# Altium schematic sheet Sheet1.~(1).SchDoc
size A; SheetNumber: 1; SheetTotal: 1
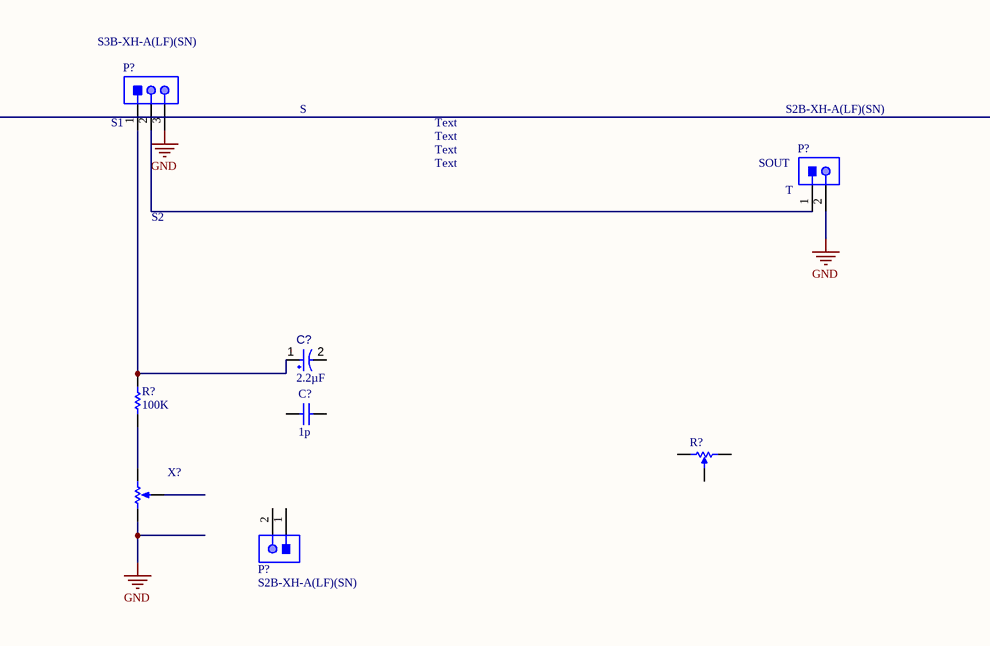
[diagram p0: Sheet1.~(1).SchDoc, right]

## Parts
(Parts that share a designator on the sheet are numbered #1, #2 ... from top to bottom, then left to right.)
C?#1  value 2.2µF  [CAPPR55-200-1100X500X1200]  (hidden comment: ECA1HM2R2)
C?#2  value 1p  (hidden comment: Capacitor)
P?#1  S3B-XH-A(LF)(SN)  [JST-S3B-XH-A(LF)(SN)_V]
P?#2  S2B-XH-A(LF)(SN)  [JST-S2B-XH-A(LF)(SN)_V]
P?#3  S2B-XH-A(LF)(SN)  [JST-S2B-XH-A(LF)(SN)_V]
R?#1  value 100K  (hidden comment: Resistor)
R?#2  3296W-1-102LF  [BOUR-3296W-1-3]  (value not drawn)
X?  Potentiometer  (value not drawn)

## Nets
GND: P?#1.3 P?#2.2 X?.1(TOP)
NetC?#1_1: C?#1.1 P?#1.1 R?#1.2
NetP?#1_2: P?#1.2 P?#2.1
NetR?#1_1: R?#1.1 X?.2(BOT)

Not connected (* = marked no-connect by the designer): C?#1 2; C?#2 1 2; P?#3 1 2; R?#2 1(A) 2(B) 3(TAP); X? 3(TAP)

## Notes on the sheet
- (near P?#1) S1
- S
- Text
- (near P?#2) SOUT
- (near P?#2) T
- S2

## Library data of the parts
C?#1 = CMP-001-00029-7: Aluminum Electrolytic Capacitor, 2.2 uF, +/- 20%, 50 V, -40 to 85 degC, 2-Pin THD, RoHS, Bulk; Manufacturer: Panasonic; Voltage Rating: 50V; Ripple Current: 20mA
C?#2 = Capacitor: SimulationGenericComponent: True
P?#1 = CMP-002-00033-2: Male Header, Pitch 2.5 mm, 1 x 3 Position, Height 6.1 mm, Tail Length 3.4 mm, -25 to 85 degC, RoHS, Bulk; Manufacturer: JST
P?#2 P?#3 = CMP-002-00032-2: Male Header, Pitch 2.5 mm, 1 x 2 Position, Height 6.1 mm, Tail Length 3.4 mm, -25 to 85 degC, RoHS, Bulk; Manufacturer: JST
R?#1 = Resistor: TC1: 0; SimulationGenericComponent: True
R?#2 = CMP-009-00037-2: Square Trimpot(R) Trimming Potentiometer, 1000 Ohm, -55 to 125 degC, 3-Pin THD, RoHS, Tube; Manufacturer: Bourns; Power: 500mW; Tolerance: 10%; Voltage Rating: 300V; Resistance: 1k
X? = Potentiometer: value: 1k; position: 0.5; SimulationGenericComponent: True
